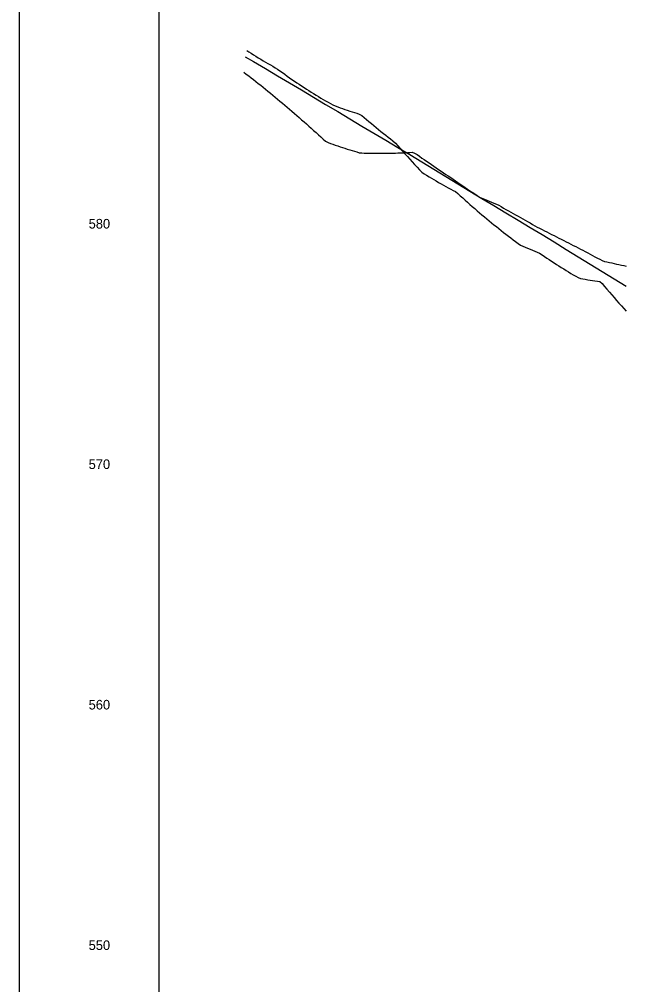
# Model space of a CAD drawing. Extents: x 1733822 to 1737718, y 1214897 to 1219897.
# Drawn here: x 1733821.6 to 1734073.8, y 1218384.3 to 1218785.8 of the extents above; entities that cross this region are included whole.
import ezdxf

# ---------------------------------------------------------------- set-up
doc = ezdxf.new("R2010")
doc.units = 0
for name, color, linetype in [('Default', 7, 'Continuous'), ('RD_DDB_ElevTX', 7, 'Continuous'), ('RD_DDB_Profile_EX', 7, 'Continuous'), ('RD_Sketch1', 7, 'Continuous'), ('RD_Sketch2', 7, 'Continuous'), ('RD_Sketch8', 7, 'Continuous')]:
    doc.layers.add(name, color=color, linetype=linetype)

msp = doc.modelspace()

# ---------------------------------------------------------------- linework, layer by layer
at = {"layer": 'Default'}
msp.add_line((1733879.77, 1217396.76), (1733879.77, 1219896.76), dxfattribs=at)
at = {"layer": 'RD_DDB_Profile_EX'}
msp.add_lwpolyline([(1733915.49, 1218770.18), (1733918.97, 1218768.18), (1733923.97, 1218765.25), (1733928.97, 1218762.31), (1733933.97, 1218759.36), (1733938.97, 1218756.39), (1733943.97, 1218753.41), (1733948.97, 1218750.41), (1733953.97, 1218747.4), (1733958.97, 1218744.38), (1733963.97, 1218741.36), (1733968.97, 1218738.41), (1733973.97, 1218735.46), (1733978.97, 1218732.48), (1733983.97, 1218729.49), (1733988.97, 1218726.49), (1733993.97, 1218723.47), (1733998.97, 1218720.44), (1734003.97, 1218717.4), (1734008.97, 1218714.35), (1734013.97, 1218711.3), (1734018.97, 1218708.3), (1734023.97, 1218705.29), (1734028.97, 1218702.26), (1734033.97, 1218699.23), (1734038.97, 1218696.24), (1734043.97, 1218693.18), (1734048.97, 1218690.11), (1734053.97, 1218687.02), (1734058.97, 1218683.92), (1734063.97, 1218680.88), (1734068.97, 1218677.82), (1734073.97, 1218674.74)], dxfattribs=at)
at = {"layer": 'RD_Sketch1'}
for points in [[(1733916.15, 1218772.83), (1733916.97, 1218772.3), (1733917.97, 1218771.65), (1733918.97, 1218771.02), (1733919.97, 1218770.39), (1733920.97, 1218769.77), (1733921.97, 1218769.16), (1733922.97, 1218768.56), (1733923.97, 1218767.96), (1733924.97, 1218767.37), (1733925.97, 1218766.79), (1733926.97, 1218766.22), (1733927.97, 1218765.65), (1733928.97, 1218765.1), (1733929.97, 1218764.37), (1733930.97, 1218763.63), (1733931.97, 1218762.91), (1733932.97, 1218762.19), (1733933.97, 1218761.48), (1733934.97, 1218760.78), (1733935.97, 1218760.09), (1733936.97, 1218759.41), (1733937.97, 1218758.73), (1733938.97, 1218758.07), (1733939.97, 1218757.41), (1733940.97, 1218756.76), (1733941.97, 1218756.12), (1733942.97, 1218755.49), (1733943.97, 1218754.86), (1733944.97, 1218754.24), (1733945.97, 1218753.64), (1733946.97, 1218753.04), (1733947.97, 1218752.45), (1733948.97, 1218751.86), (1733949.97, 1218751.29), (1733950.97, 1218750.72), (1733951.97, 1218750.16), (1733952.97, 1218749.72), (1733953.97, 1218749.34), (1733954.97, 1218748.98), (1733955.97, 1218748.62), (1733956.97, 1218748.28), (1733957.97, 1218747.94), (1733958.97, 1218747.61), (1733959.97, 1218747.29), (1733960.97, 1218746.97), (1733961.97, 1218746.67), (1733962.97, 1218746.38), (1733963.97, 1218745.77), (1733964.97, 1218744.9), (1733965.97, 1218744.05), (1733966.97, 1218743.21), (1733967.97, 1218742.38), (1733968.97, 1218741.55), (1733969.97, 1218740.73), (1733970.97, 1218739.93), (1733971.97, 1218739.13), (1733972.97, 1218738.34), (1733973.97, 1218737.56), (1733974.97, 1218736.79), (1733975.97, 1218736.02), (1733976.97, 1218735.27), (1733977.97, 1218734.29), (1733978.97, 1218733.15), (1733979.97, 1218732.01), (1733980.97, 1218730.89), (1733981.97, 1218729.77), (1733982.97, 1218728.65), (1733983.97, 1218727.55), (1733984.97, 1218726.45), (1733985.97, 1218725.36), (1733986.97, 1218724.28), (1733987.97, 1218723.2), (1733988.97, 1218722.18), (1733989.97, 1218721.56), (1733990.97, 1218720.94), (1733991.97, 1218720.33), (1733992.97, 1218719.73), (1733993.97, 1218719.13), (1733994.97, 1218718.54), (1733995.97, 1218717.96), (1733996.97, 1218717.39), (1733997.97, 1218716.82), (1733998.97, 1218716.26), (1733999.97, 1218715.71), (1734000.97, 1218715.16), (1734001.97, 1218714.63), (1734002.97, 1218714.1), (1734003.97, 1218713.33), (1734004.97, 1218712.42), (1734005.97, 1218711.51), (1734006.97, 1218710.6), (1734007.97, 1218709.7), (1734008.97, 1218708.81), (1734009.97, 1218707.92), (1734010.97, 1218707.05), (1734011.97, 1218706.17), (1734012.97, 1218705.32), (1734013.97, 1218704.47), (1734014.97, 1218703.64), (1734015.97, 1218702.81)], [(1734015.97, 1218702.81), (1734016.97, 1218701.99), (1734017.97, 1218701.17), (1734018.97, 1218700.36), (1734019.97, 1218699.56), (1734020.97, 1218698.76), (1734021.97, 1218697.97), (1734022.97, 1218697.18), (1734023.97, 1218696.4), (1734024.97, 1218695.63), (1734025.97, 1218694.86), (1734026.97, 1218694.1), (1734027.97, 1218693.35), (1734028.97, 1218692.6), (1734029.97, 1218691.86), (1734030.97, 1218691.42), (1734031.97, 1218690.99), (1734032.97, 1218690.57), (1734033.97, 1218690.16), (1734034.97, 1218689.75), (1734035.97, 1218689.36), (1734036.97, 1218688.96), (1734037.97, 1218688.54), (1734038.97, 1218687.85), (1734039.97, 1218687.17), (1734040.97, 1218686.49), (1734041.97, 1218685.82), (1734042.97, 1218685.16), (1734043.97, 1218684.51), (1734044.97, 1218683.86), (1734045.97, 1218683.22), (1734046.97, 1218682.59), (1734047.97, 1218681.96), (1734048.97, 1218681.35), (1734049.97, 1218680.74), (1734050.97, 1218680.13), (1734051.97, 1218679.53), (1734052.97, 1218678.95), (1734053.97, 1218678.36), (1734054.97, 1218678.03), (1734055.97, 1218677.84), (1734056.97, 1218677.67), (1734057.97, 1218677.5), (1734058.97, 1218677.35), (1734059.97, 1218677.2), (1734060.97, 1218677.06), (1734061.97, 1218676.92), (1734062.97, 1218676.8), (1734063.97, 1218675.88), (1734064.97, 1218674.69), (1734065.97, 1218673.52), (1734066.97, 1218672.35), (1734067.97, 1218671.19), (1734068.97, 1218670.05), (1734069.97, 1218668.9), (1734070.97, 1218667.77), (1734071.97, 1218666.65), (1734072.97, 1218665.53), (1734073.97, 1218664.43)]]:
    msp.add_lwpolyline(points, dxfattribs=at)
at = {"layer": 'RD_Sketch2'}
for points in [[(1733914.88, 1218763.81), (1733914.97, 1218763.74), (1733915.97, 1218762.98), (1733916.97, 1218762.22), (1733917.97, 1218761.46), (1733918.97, 1218760.69), (1733919.97, 1218759.92), (1733920.97, 1218759.14), (1733921.97, 1218758.34), (1733922.97, 1218757.53), (1733923.97, 1218756.72), (1733924.97, 1218755.9), (1733925.97, 1218755.08), (1733926.97, 1218754.26), (1733927.97, 1218753.43), (1733928.97, 1218752.59), (1733929.97, 1218751.75), (1733930.97, 1218750.91), (1733931.97, 1218750.07), (1733932.97, 1218749.21), (1733933.97, 1218748.36), (1733934.97, 1218747.5), (1733935.97, 1218746.64), (1733936.97, 1218745.77), (1733937.97, 1218744.9), (1733938.97, 1218744.02), (1733939.97, 1218743.14), (1733940.97, 1218742.26), (1733941.97, 1218741.37), (1733942.97, 1218740.47), (1733943.97, 1218739.58), (1733944.97, 1218738.68), (1733945.97, 1218737.77), (1733946.97, 1218736.86), (1733947.97, 1218735.95), (1733948.97, 1218735.03), (1733949.97, 1218734.5), (1733950.97, 1218734.14), (1733951.97, 1218733.8), (1733952.97, 1218733.45), (1733953.97, 1218733.12), (1733954.97, 1218732.78), (1733955.97, 1218732.46), (1733956.97, 1218732.13), (1733957.97, 1218731.81), (1733958.97, 1218731.5), (1733959.97, 1218731.19), (1733960.97, 1218730.89), (1733961.97, 1218730.59), (1733962.97, 1218730.29), (1733963.97, 1218730.21), (1733964.97, 1218730.17), (1733965.97, 1218730.14), (1733966.97, 1218730.12), (1733967.97, 1218730.09), (1733968.97, 1218730.08), (1733969.97, 1218730.07), (1733970.97, 1218730.06), (1733971.97, 1218730.06), (1733972.97, 1218730.06), (1733973.97, 1218730.07), (1733974.97, 1218730.08), (1733975.97, 1218730.1), (1733976.97, 1218730.12), (1733977.97, 1218730.15), (1733978.97, 1218730.18), (1733979.97, 1218730.21), (1733980.97, 1218730.25), (1733981.97, 1218730.3), (1733982.97, 1218730.35), (1733983.97, 1218730.4), (1733984.97, 1218730.46), (1733985.97, 1218730.15), (1733986.97, 1218729.53), (1733987.97, 1218728.8), (1733988.97, 1218728.09), (1733989.97, 1218727.41), (1733990.97, 1218726.73), (1733991.97, 1218726.05), (1733992.97, 1218725.37), (1733993.97, 1218724.69), (1733994.97, 1218724.01), (1733995.97, 1218723.33), (1733996.97, 1218722.65), (1733997.97, 1218721.97), (1733998.97, 1218721.29), (1733999.97, 1218720.62), (1734000.97, 1218719.94), (1734001.97, 1218719.26), (1734002.97, 1218718.58), (1734003.97, 1218717.9), (1734004.97, 1218717.22), (1734005.97, 1218716.54), (1734006.97, 1218715.86), (1734007.97, 1218715.18), (1734008.97, 1218714.5), (1734009.97, 1218713.82), (1734010.97, 1218713.14), (1734011.97, 1218712.46), (1734012.97, 1218711.84), (1734013.97, 1218711.43)], [(1734013.97, 1218711.43), (1734014.97, 1218711.02), (1734015.97, 1218710.6), (1734016.97, 1218710.19), (1734017.97, 1218709.78), (1734018.97, 1218709.36), (1734019.97, 1218708.95), (1734020.97, 1218708.44), (1734021.97, 1218707.87), (1734022.97, 1218707.3), (1734023.97, 1218706.74), (1734024.97, 1218706.17), (1734025.97, 1218705.6), (1734026.97, 1218705.04), (1734027.97, 1218704.47), (1734028.97, 1218703.91), (1734029.97, 1218703.34), (1734030.97, 1218702.77), (1734031.97, 1218702.21), (1734032.97, 1218701.64), (1734033.97, 1218701.08), (1734034.97, 1218700.51), (1734035.97, 1218699.95), (1734036.97, 1218699.39), (1734037.97, 1218698.88), (1734038.97, 1218698.36), (1734039.97, 1218697.85), (1734040.97, 1218697.34), (1734041.97, 1218696.83), (1734042.97, 1218696.32), (1734043.97, 1218695.81), (1734044.97, 1218695.3), (1734045.97, 1218694.79), (1734046.97, 1218694.28), (1734047.97, 1218693.77), (1734048.97, 1218693.26), (1734049.97, 1218692.75), (1734050.97, 1218692.24), (1734051.97, 1218691.74), (1734052.97, 1218691.23), (1734053.97, 1218690.72), (1734054.97, 1218690.21), (1734055.97, 1218689.7), (1734056.97, 1218689.2), (1734057.97, 1218688.66), (1734058.97, 1218688.12), (1734059.97, 1218687.58), (1734060.97, 1218687.04), (1734061.97, 1218686.5), (1734062.97, 1218685.96), (1734063.97, 1218685.42), (1734064.97, 1218685.09), (1734065.97, 1218684.87), (1734066.97, 1218684.65), (1734067.97, 1218684.44), (1734068.97, 1218684.22), (1734069.97, 1218684.01), (1734070.97, 1218683.79), (1734071.97, 1218683.58), (1734072.97, 1218683.36), (1734073.97, 1218683.15)]]:
    msp.add_lwpolyline(points, dxfattribs=at)
at = {"layer": 'RD_Sketch8'}
msp.add_lwpolyline([(1733821.56, 1217253.41), (1737421.56, 1217253.41), (1737421.56, 1219453.41), (1733821.56, 1219453.41)], close=True, dxfattribs=at)

# ---------------------------------------------------------------- texts
at = {"layer": 'RD_DDB_ElevTX'}
for s, p in [('580', (1733850.4, 1218698.76)), ('580', (1733850.4, 1218698.76)), ('580', (1733850.4, 1218698.76)), ('580', (1733850.4, 1218698.76)), ('580', (1733850.4, 1218698.76)), ('570', (1733850.4, 1218598.76)), ('570', (1733850.4, 1218598.76)), ('570', (1733850.4, 1218598.76)), ('570', (1733850.4, 1218598.76)), ('570', (1733850.4, 1218598.76)), ('560', (1733850.4, 1218498.76)), ('560', (1733850.4, 1218498.76)), ('560', (1733850.4, 1218498.76)), ('560', (1733850.4, 1218498.76)), ('560', (1733850.4, 1218498.76)), ('550', (1733850.4, 1218398.76)), ('550', (1733850.4, 1218398.76)), ('550', (1733850.4, 1218398.76)), ('550', (1733850.4, 1218398.76)), ('550', (1733850.4, 1218398.76))]:
    msp.add_text(s, height=4, dxfattribs=at).set_placement(p)

doc.saveas('drawing.dxf')
